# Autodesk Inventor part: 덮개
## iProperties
Company: 한국ATC센터
Created: 2015-04
Part Number: 덮개
Document SubType Name: Modeling
Designer: KYOUNG IL JANG
Density: 2.71 g/cm^3
Material: 알루미늄-6061
Author: KYOUNG IL JANG
